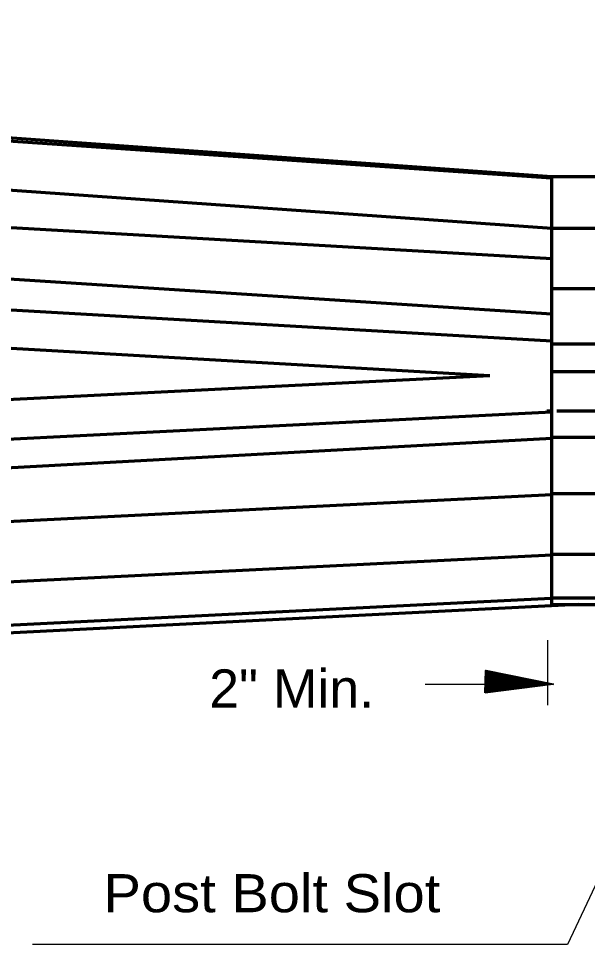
# Model space of a CAD drawing. Extents: x 895.6 to 930.4, y -2278.6 to -2254.7.
# Drawn here: x 919.509 to 921.428, y -2263.412 to -2260.289 of the extents above; entities that cross this region are included whole.
import ezdxf

# ---------------------------------------------------------------- set-up
doc = ezdxf.new("R2010")
doc.units = 0
doc.header["$LTSCALE"] = 0.051
doc.layers.add('1', color=7, linetype='Continuous', lineweight=70)
doc.layers.add('3', color=7, linetype='Continuous', lineweight=40)

msp = doc.modelspace()

# ---------------------------------------------------------------- hatches: boundary and pattern name
at = {"layer": '3'}
for points in [[(921.08283, -2262.56367), (921.08533, -2262.48775), (921.31158, -2262.53342), (921.31158, -2262.53342)], [(921.08408, -2262.55975), (921.08625, -2262.49167), (921.28975, -2262.53267), (921.28975, -2262.53267)], [(921.08508, -2262.55642), (921.08708, -2262.49508), (921.27025, -2262.53208), (921.27025, -2262.53208)], [(921.08608, -2262.55333), (921.08783, -2262.49825), (921.25267, -2262.53142), (921.25267, -2262.53142)], [(921.08675, -2262.55083), (921.08858, -2262.50117), (921.23683, -2262.53092), (921.23683, -2262.53092)], [(921.08775, -2262.54825), (921.08917, -2262.50358), (921.22267, -2262.53058), (921.22267, -2262.53058)], [(921.08825, -2262.54608), (921.08958, -2262.50567), (921.20983, -2262.52992), (921.20983, -2262.52992)], [(921.08892, -2262.54417), (921.09008, -2262.50783), (921.19817, -2262.52975), (921.19817, -2262.52975)], [(921.08933, -2262.54233), (921.09058, -2262.50958), (921.18783, -2262.52917), (921.18783, -2262.52917)], [(921.08992, -2262.54067), (921.09108, -2262.51117), (921.17858, -2262.52908), (921.17858, -2262.52908)], [(921.09042, -2262.53917), (921.09133, -2262.51283), (921.17008, -2262.52867), (921.17008, -2262.52867)], [(921.09075, -2262.53783), (921.09167, -2262.51417), (921.16258, -2262.52825), (921.16258, -2262.52825)], [(921.09125, -2262.53675), (921.09183, -2262.51525), (921.15558, -2262.52817), (921.15558, -2262.52817)], [(921.09167, -2262.53558), (921.09217, -2262.51633), (921.14967, -2262.52808), (921.14967, -2262.52808)], [(921.09183, -2262.53467), (921.09242, -2262.51733), (921.14408, -2262.52783), (921.14408, -2262.52783)], [(921.09217, -2262.53383), (921.09258, -2262.51817), (921.13917, -2262.52742), (921.13917, -2262.52742)], [(921.09233, -2262.53308), (921.09283, -2262.51883), (921.13467, -2262.52733), (921.13467, -2262.52733)], [(921.09258, -2262.53225), (921.09292, -2262.51967), (921.13075, -2262.52725), (921.13075, -2262.52725)], [(921.09283, -2262.53183), (921.09317, -2262.52033), (921.12717, -2262.52725), (921.12717, -2262.52725)], [(921.09308, -2262.53133), (921.09333, -2262.52092), (921.12392, -2262.52725), (921.12392, -2262.52725)], [(921.09325, -2262.53092), (921.09358, -2262.52175), (921.12108, -2262.52733), (921.12108, -2262.52733)], [(921.09325, -2262.53042), (921.09358, -2262.52217), (921.11842, -2262.52725), (921.11842, -2262.52725)], [(921.09342, -2262.52992), (921.09375, -2262.52258), (921.11608, -2262.52692), (921.11608, -2262.52692)], [(921.09358, -2262.52975), (921.09383, -2262.52308), (921.11392, -2262.52708), (921.11392, -2262.52708)]]:
    msp.add_hatch(color=256, dxfattribs=at).paths.add_polyline_path(points)

# ---------------------------------------------------------------- linework, layer by layer
at = {"layer": '1'}
for p, q in [((913.85217, -2260.28858), (921.30733, -2260.82175)), ((913.85217, -2260.31833), (921.30483, -2260.82608)), ((913.85217, -2260.46825), (921.30733, -2260.99608)), ((921.30733, -2262.26483), (921.30733, -2260.82175)), ((921.30733, -2260.82175), (922.81058, -2260.82175)), ((921.30733, -2261.09925), (917.91892, -2260.90392)), ((921.30733, -2261.37642), (913.84675, -2260.95042)), ((921.30733, -2260.99608), (922.81058, -2260.99608)), ((921.30733, -2261.28567), (917.88075, -2261.06475)), ((921.09808, -2261.49383), (913.83925, -2261.08083)), ((921.30733, -2261.19933), (922.81058, -2261.19933)), ((921.30733, -2261.38625), (922.81058, -2261.38625)), ((921.30733, -2261.47942), (921.83808, -2261.47942)), ((921.09808, -2261.49383), (913.84075, -2261.85333)), ((921.30733, -2261.61683), (917.88308, -2261.78708)), ((921.30175, -2261.61267), (921.29025, -2261.61267)), ((921.78592, -2261.61267), (921.32442, -2261.61267)), ((921.30733, -2261.70483), (917.90675, -2261.89108)), ((921.30733, -2261.70042), (921.75167, -2261.70042)), ((921.30733, -2261.89558), (913.85217, -2262.26483)), ((921.30733, -2261.89125), (922.81058, -2261.89125)), ((921.30733, -2262.09933), (913.85217, -2262.46558)), ((921.30733, -2262.09508), (922.81058, -2262.09508)), ((913.85217, -2262.61567), (921.30483, -2262.24375)), ((922.81058, -2262.24375), (921.30483, -2262.24375)), ((921.39667, -2262.26483), (913.85217, -2262.64575)), ((921.30175, -2262.26483), (922.81058, -2262.26483))]:
    msp.add_line(p, q, dxfattribs=at)
at = {"layer": '1', "lineweight": 25}
for p, q in [((922.13808, -2261.75225), (921.36075, -2263.412)), ((921.29458, -2262.60458), (921.29458, -2262.38583)), ((921.23958, -2262.53483), (920.88033, -2262.53483)), ((921.36075, -2263.412), (919.5565, -2263.412))]:
    msp.add_line(p, q, dxfattribs=at)
at = {"layer": '3'}
for points in [[(921.08283, -2262.56367), (921.08533, -2262.48775), (921.31158, -2262.53342), (921.31158, -2262.53342)], [(921.08408, -2262.55975), (921.08625, -2262.49167), (921.28975, -2262.53267), (921.28975, -2262.53267)], [(921.08508, -2262.55642), (921.08708, -2262.49508), (921.27025, -2262.53208), (921.27025, -2262.53208)], [(921.08608, -2262.55333), (921.08783, -2262.49825), (921.25267, -2262.53142), (921.25267, -2262.53142)], [(921.08675, -2262.55083), (921.08858, -2262.50117), (921.23683, -2262.53092), (921.23683, -2262.53092)], [(921.08775, -2262.54825), (921.08917, -2262.50358), (921.22267, -2262.53058), (921.22267, -2262.53058)], [(921.08825, -2262.54608), (921.08958, -2262.50567), (921.20983, -2262.52992), (921.20983, -2262.52992)], [(921.08892, -2262.54417), (921.09008, -2262.50783), (921.19817, -2262.52975), (921.19817, -2262.52975)], [(921.08933, -2262.54233), (921.09058, -2262.50958), (921.18783, -2262.52917), (921.18783, -2262.52917)], [(921.08992, -2262.54067), (921.09108, -2262.51117), (921.17858, -2262.52908), (921.17858, -2262.52908)], [(921.09042, -2262.53917), (921.09133, -2262.51283), (921.17008, -2262.52867), (921.17008, -2262.52867)], [(921.09075, -2262.53783), (921.09167, -2262.51417), (921.16258, -2262.52825), (921.16258, -2262.52825)], [(921.09125, -2262.53675), (921.09183, -2262.51525), (921.15558, -2262.52817), (921.15558, -2262.52817)], [(921.09167, -2262.53558), (921.09217, -2262.51633), (921.14967, -2262.52808), (921.14967, -2262.52808)], [(921.09183, -2262.53467), (921.09242, -2262.51733), (921.14408, -2262.52783), (921.14408, -2262.52783)], [(921.09217, -2262.53383), (921.09258, -2262.51817), (921.13917, -2262.52742), (921.13917, -2262.52742)], [(921.09233, -2262.53308), (921.09283, -2262.51883), (921.13467, -2262.52733), (921.13467, -2262.52733)], [(921.09258, -2262.53225), (921.09292, -2262.51967), (921.13075, -2262.52725), (921.13075, -2262.52725)], [(921.09283, -2262.53183), (921.09317, -2262.52033), (921.12717, -2262.52725), (921.12717, -2262.52725)], [(921.09308, -2262.53133), (921.09333, -2262.52092), (921.12392, -2262.52725), (921.12392, -2262.52725)], [(921.09325, -2262.53092), (921.09358, -2262.52175), (921.12108, -2262.52733), (921.12108, -2262.52733)], [(921.09325, -2262.53042), (921.09358, -2262.52217), (921.11842, -2262.52725), (921.11842, -2262.52725)], [(921.09342, -2262.52992), (921.09375, -2262.52258), (921.11608, -2262.52692), (921.11608, -2262.52692)], [(921.09358, -2262.52975), (921.09383, -2262.52308), (921.11392, -2262.52708), (921.11392, -2262.52708)]]:
    msp.add_lwpolyline(points, close=True, dxfattribs=at)

# ---------------------------------------------------------------- texts
at = {"layer": '1'}
for s, width, p in [('2" Min.', 1.05, (920.15233, -2262.61267)), ('Post Bolt Slot', 1.1, (919.79583, -2263.30333))]:
    msp.add_text(s, height=0.1286, dxfattribs=dict(at, width=width)).set_placement(p)

doc.saveas('drawing.dxf')
